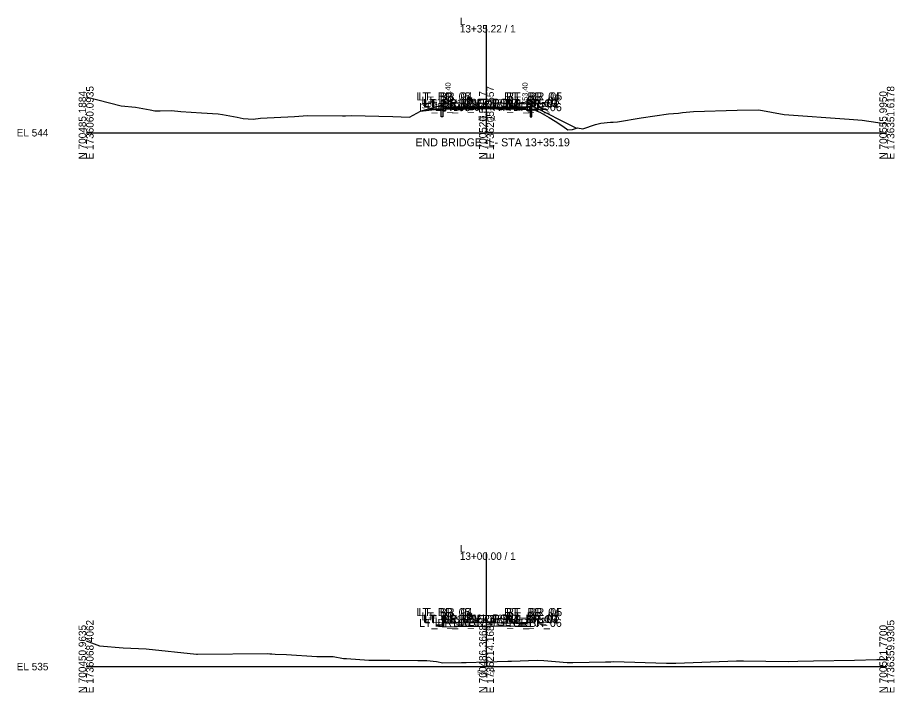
# Model space of a CAD drawing. Extents: x -26 to 697, y -10 to 2642.
# Drawn here: x -25.7 to 302.8, y 1390.3 to 1643.2 of the extents above; entities that cross this region are included whole.
import ezdxf

# ---------------------------------------------------------------- set-up
doc = ezdxf.new("R2010")
doc.units = 0
for name, color, linetype in [('Default', 7, 'Continuous'), ('Exist Cross Section Cell', 7, 'Continuous'), ('Exist XS Center Line Elevation Label', 7, 'Continuous'), ('Exist XS Ground Line', 7, 'Continuous'), ('Prop CMT Concrete Structures', 7, 'Continuous'), ('Prop CMT Guardrail SBG', 7, 'Continuous'), ('Prop CMT Pvmt Course 1', 7, 'Continuous'), ('Prop CMT Pvmt Course 2', 7, 'Continuous'), ('Prop CMT Pvmt Surface', 7, 'Continuous'), ('Prop CMT Pvmt Surface Shoulder', 7, 'Continuous'), ('Prop CMT Shld Paved Course 1', 7, 'Continuous'), ('Prop CMT Shld Paved Course 2', 7, 'Continuous'), ('Prop CMT Slope Grass', 7, 'Continuous'), ('Prop CMT Subgrade Earthwork', 7, 'Continuous'), ('Prop XS Hydro Elevations', 7, 'Continuous'), ('Prop XS SE Text', 7, 'Continuous'), ('Prop XS Side Slope Text', 7, 'Continuous')]:
    doc.layers.add(name, color=color, linetype=linetype)

msp = doc.modelspace()

# ---------------------------------------------------------------- linework, layer by layer
at = {"layer": 'Exist Cross Section Cell'}
for p, q in [((150, 1600), (150, 1640.35)), ((0, 1600), (150, 1600)), ((150, 1600), (300, 1600)), ((150, 1400), (150, 1442.78)), ((0, 1400), (150, 1400)), ((150, 1400), (300, 1400))]:
    msp.add_line(p, q, dxfattribs=at)
at = {"layer": 'Exist XS Center Line Elevation Label'}
for p, q in [((133.5, 1414.87), (133.5, 1416.22)), ((133.58, 1416.22), (133.58, 1418.91)), ((134.58, 1416.22), (134.58, 1418.91)), ((165.42, 1416.22), (165.42, 1418.91)), ((166.42, 1416.22), (166.42, 1418.91)), ((166.5, 1414.87), (166.5, 1416.22))]:
    msp.add_line(p, q, dxfattribs=at)
at = {"layer": 'Exist XS Ground Line'}
for points in [[(0, 1613.45), (13.1, 1610.13), (18.5, 1609.6), (23.97, 1608.58), (25.74, 1608.24), (27.68, 1608.25), (31.96, 1608.28), (35.46, 1607.94), (43.25, 1607.45), (49.53, 1607.02), (51.14, 1606.85), (56.59, 1605.78), (58.88, 1605.34), (62.57, 1605.06), (65.28, 1605.43), (78.08, 1606.05), (83, 1606.4), (96.09, 1606.37), (97.14, 1606.36), (99.25, 1606.45), (114.96, 1606.11), (121.2, 1605.8), (125.32, 1608.1), (133.81, 1609.09), (134.99, 1609.33), (138.11, 1609.4), (140.28, 1609.45), (143.28, 1609.41), (149.53, 1609.42), (150, 1609.41), (156.31, 1609.37), (159.15, 1609.48), (159.41, 1609.35), (160.65, 1609.15), (162.87, 1608.94), (165.72, 1608.86), (167.9, 1608.75), (169, 1608.07), (170, 1607.73), (173.49, 1605.72), (175.78, 1604.35), (178.62, 1602.48), (180.43, 1601.03), (182.17, 1601.27), (184.15, 1601.84), (186.07, 1601.52), (190.8, 1603.09), (192.86, 1603.63), (196.51, 1603.93), (197.51, 1604), (199.02, 1604.1), (207.98, 1605.6), (218.16, 1607.06), (221.92, 1607.36), (223.46, 1607.58), (227.61, 1607.92), (243.88, 1608.44), (252.01, 1608.52), (261.56, 1606.89), (285.88, 1605.07), (287.48, 1604.94), (290.69, 1604.67), (300, 1603.28)], [(0, 1409.61), (5.04, 1407.8), (13.87, 1407.06), (22.53, 1406.6), (41.36, 1404.69), (41.71, 1404.65), (68.09, 1404.85), (68.79, 1404.8), (69.54, 1404.83), (70.77, 1404.71), (75.02, 1404.55), (86.47, 1403.82), (92.61, 1403.8), (96.47, 1403.04), (97.58, 1402.99), (105.9, 1402.43), (113.82, 1402.43), (124.24, 1402.29), (127.66, 1402.24), (131.23, 1401.94), (133.68, 1401.41), (140.66, 1401.56), (142.41, 1401.57), (150, 1401.77), (157.96, 1401.97), (159.37, 1402), (168.95, 1402.44), (171.53, 1402.34), (180.24, 1401.48), (182.32, 1401.49), (194.54, 1401.81), (196.6, 1401.79), (197.52, 1401.85), (217.48, 1401.27), (218.69, 1401.26), (219.86, 1401.26), (220.97, 1401.24), (243.6, 1402.2), (244.94, 1402.19), (246.29, 1402.14), (263.04, 1401.95), (266.7, 1401.98), (272.51, 1402.19), (287.87, 1402.36), (296.21, 1402.61), (298.63, 1402.69), (300, 1402.69)]]:
    msp.add_lwpolyline(points, dxfattribs=at)
at = {"layer": 'Prop CMT Concrete Structures'}
for p, q in [((133.92, 1608.24), (134.58, 1608.24)), ((166.08, 1608.24), (165.42, 1608.24)), ((133.5, 1416.22), (133.58, 1416.22)), ((134.58, 1418.91), (133.58, 1418.91)), ((165.42, 1418.91), (166.42, 1418.91)), ((166.5, 1416.22), (166.42, 1416.22))]:
    msp.add_line(p, q, dxfattribs=at)
for points in [[(136.92, 1609.49), (134.58, 1609.4), (133.92, 1609.74)], [(133.92, 1609.74), (133.92, 1608.24)], [(134.58, 1609.4), (133.92, 1609.74)], [(134.58, 1608.24), (134.58, 1609.4)], [(165.42, 1609.4), (166.08, 1609.74)], [(165.42, 1608.24), (165.42, 1609.4)], [(166.08, 1609.74), (166.08, 1608.24)], [(150, 1416.53), (139, 1416.31), (134.58, 1416.22)], [(150, 1415.2), (150, 1416.53)], [(150, 1415.2), (150, 1416.53)], [(150, 1416.53), (161, 1416.31), (165.42, 1416.22)], [(133.5, 1414.87), (139, 1414.98), (150, 1415.2)], [(166.5, 1414.87), (161, 1414.98), (150, 1415.2)]]:
    msp.add_lwpolyline(points, dxfattribs=at)
at = {"layer": 'Prop CMT Guardrail SBG'}
for points in [[(132.98, 1605.9), (132.98, 1611.9)], [(132.98, 1611.9), (134.31, 1611.9), (134.58, 1611.61)], [(134.58, 1611.02), (134.31, 1610.73), (133.65, 1610.73)], [(133.65, 1610.73), (133.65, 1605.9)], [(134.58, 1611.61), (134.31, 1611.31)], [(134.31, 1611.31), (134.58, 1611.02)], [(167.02, 1611.9), (165.69, 1611.9), (165.42, 1611.61)], [(165.42, 1611.61), (165.69, 1611.31)], [(165.69, 1611.31), (165.42, 1611.02)], [(165.42, 1611.02), (165.69, 1610.73), (166.35, 1610.73)], [(166.35, 1610.73), (166.35, 1605.9)], [(167.02, 1605.9), (167.02, 1611.9)], [(133.65, 1605.9), (132.98, 1605.9)], [(166.35, 1605.9), (167.02, 1605.9)]]:
    msp.add_lwpolyline(points, dxfattribs=at)
at = {"layer": 'Prop CMT Pvmt Course 1'}
for points in [[(150, 1609.75), (139, 1609.53)], [(139, 1609.32), (150, 1609.54)], [(139, 1609.53), (139, 1609.32)], [(150, 1609.54), (150, 1609.75)], [(150, 1609.75), (161, 1609.53)], [(150, 1609.54), (150, 1609.75)], [(161, 1609.32), (150, 1609.54)], [(161, 1609.53), (161, 1609.32)]]:
    msp.add_lwpolyline(points, dxfattribs=at)
msp.add_lwpolyline([(150, 1609.54), (150, 1609.65), (150, 1609.65), (150, 1609.54)], close=True, dxfattribs=at)
msp.add_lwpolyline([(150, 1609.54), (150, 1609.65), (150, 1609.65), (150, 1609.54)], close=True, dxfattribs=at)
at = {"layer": 'Prop CMT Pvmt Course 2'}
for points in [[(150, 1609.54), (139, 1609.32)], [(139, 1609.32), (139, 1608.87)], [(139, 1608.87), (150, 1609.09)], [(150, 1609.09), (150, 1609.54)], [(150, 1609.09), (150, 1609.54)], [(150, 1609.54), (161, 1609.32)], [(161, 1608.87), (150, 1609.09)], [(161, 1609.32), (161, 1608.87)]]:
    msp.add_lwpolyline(points, dxfattribs=at)
at = {"layer": 'Prop CMT Pvmt Surface'}
for points in [[(150, 1609.75), (139, 1609.53)], [(150, 1609.75), (161, 1609.53)]]:
    msp.add_lwpolyline(points, dxfattribs=at)
at = {"layer": 'Prop CMT Pvmt Surface Shoulder'}
for points in [[(136.92, 1609.49), (134.58, 1609.4)], [(139, 1609.53), (136.92, 1609.49)], [(161, 1609.53), (163.08, 1609.49)], [(163.08, 1609.49), (165.42, 1609.4)]]:
    msp.add_lwpolyline(points, dxfattribs=at)
at = {"layer": 'Prop CMT Shld Paved Course 1'}
for points in [[(139, 1609.53), (136.92, 1609.49)], [(136.92, 1609.49), (136.92, 1609.28)], [(136.92, 1609.28), (139, 1609.32)], [(139, 1609.32), (139, 1609.53)], [(161, 1609.53), (163.08, 1609.49)], [(161, 1609.32), (161, 1609.53)], [(163.08, 1609.28), (161, 1609.32)], [(163.08, 1609.49), (163.08, 1609.28)]]:
    msp.add_lwpolyline(points, dxfattribs=at)
at = {"layer": 'Prop CMT Shld Paved Course 2'}
for points in [[(139, 1609.32), (136.92, 1609.28)], [(136.92, 1609.28), (136.92, 1609.07), (136.92, 1608.82)], [(136.92, 1608.82), (139, 1608.87)], [(139, 1608.87), (139, 1609.32)], [(161, 1609.32), (163.08, 1609.28)], [(161, 1608.87), (161, 1609.32)], [(163.08, 1608.82), (161, 1608.87)], [(163.08, 1609.28), (163.08, 1609.07), (163.08, 1608.82)]]:
    msp.add_lwpolyline(points, dxfattribs=at)
at = {"layer": 'Prop CMT Slope Grass'}
for points in [[(133.92, 1609.74), (133.15, 1610.14), (125.92, 1608.17)], [(166.08, 1609.74), (166.85, 1610.14), (183.71, 1601.71)]]:
    msp.add_lwpolyline(points, dxfattribs=at)
at = {"layer": 'Prop CMT Subgrade Earthwork'}
for p, q in [((133.92, 1608.24), (133.92, 1608.82)), ((134.58, 1608.24), (133.92, 1608.24)), ((165.42, 1608.24), (166.08, 1608.24)), ((166.08, 1608.24), (166.08, 1608.82))]:
    msp.add_line(p, q, dxfattribs=at)
for points in [[(133.92, 1608.82), (128.33, 1608.82)], [(134.58, 1608.24), (134.58, 1608.82)], [(136.92, 1608.82), (134.58, 1608.82)], [(139, 1608.87), (136.92, 1608.82)], [(136.92, 1608.82), (136.92, 1608.82)], [(150, 1609.09), (139, 1608.87)], [(150, 1609.09), (161, 1608.87)], [(161, 1608.87), (163.08, 1608.82)], [(163.08, 1608.82), (163.08, 1608.82)], [(163.08, 1608.82), (165.42, 1608.82)], [(165.42, 1608.24), (165.42, 1608.82)], [(166.08, 1608.82), (169.48, 1608.82)]]:
    msp.add_lwpolyline(points, dxfattribs=at)

# ---------------------------------------------------------------- texts
at = {"layer": 'Default'}
for s, height, p in [('LT_ BR_05', 3, (123.75, 1612.11)), ('LT_ BR_04', 3, (124.46, 1612.11)), ('LT_BR_03', 3, (125.65, 1610.53)), ('RT_ BR_04', 3, (156.64, 1612.11)), ('RT_ BR_05', 3, (157.4, 1612.11)), ('RT_BR_03', 3, (157.5, 1610.53)), ('LT_BR_06', 3, (124.71, 1608.08)), ('LT_BR_02', 3, (126.29, 1609.69)), ('LT_PV1_OEOT', 3, (126.6, 1609.53)), ('LT_BR_01', 3, (126.73, 1609.44)), ('LT_BR_07', 3, (130.58, 1608.2)), ('PV1_PGL', 3, (142.41, 1609.75)), ('BR_PGL', 3, (143.26, 1608.42)), ('RT_PV1_OEOT', 3, (148.42, 1609.53)), ('RT_BR_07', 3, (152.41, 1608.2)), ('RT_BR_02', 3, (156.96, 1609.69)), ('RT_BR_01', 3, (157.39, 1609.44)), ('RT_BR_06', 3, (158.37, 1608.08)), ('-', 0.0001, (0, 1600)), ('LT_ BR_05', 3, (123.75, 1418.89)), ('LT_ BR_04', 3, (124.46, 1418.89)), ('LT_BR_03', 3, (125.65, 1417.3)), ('LT_BR_02', 3, (126.29, 1416.47)), ('LT_PV1_OEOT', 3, (126.6, 1416.31)), ('LT_BR_01', 3, (126.73, 1416.22)), ('PV1_PGL', 3, (142.41, 1416.53)), ('RT_PV1_OEOT', 3, (148.42, 1416.31)), ('RT_ BR_04', 3, (156.64, 1418.89)), ('RT_BR_02', 3, (156.96, 1416.47)), ('RT_BR_01', 3, (157.39, 1416.22)), ('RT_ BR_05', 3, (157.4, 1418.89)), ('RT_BR_03', 3, (157.5, 1417.3)), ('LT_BR_06', 3, (124.71, 1414.86)), ('LT_BR_07', 3, (130.58, 1414.98)), ('BR_PGL', 3, (143.26, 1415.2)), ('RT_BR_07', 3, (152.41, 1414.98)), ('RT_BR_06', 3, (158.37, 1414.86)), ('-', 0.0001, (0, 1400))]:
    msp.add_text(s, height=height, dxfattribs=at).set_placement(p)
at = {"layer": 'Exist Cross Section Cell'}
for s, p in [('L', (140, 1640.35)), ('13+35.22 / 1', (140, 1637.55)), ('EL 544', (-26, 1598.6)), ('L', (140, 1442.78)), ('13+00.00 / 1', (140, 1439.98)), ('EL 535', (-26, 1398.6))]:
    msp.add_text(s, height=2.8, dxfattribs=at).set_placement(p)
for s, p in [('E 1736060.0935', (2.8, 1590)), ('E 1736205.8557', (152.8, 1590)), ('E 1736351.6178', (302.8, 1590)), ('N 700485.1884', (0, 1590)), ('N 700520.5917', (150, 1590)), ('N 700555.9950', (300, 1590)), ('E 1736068.4062', (2.8, 1390)), ('E 1736214.1684', (152.8, 1390)), ('E 1736359.9305', (302.8, 1390)), ('N 700450.9635', (0, 1390)), ('N 700486.3668', (150, 1390)), ('N 700521.7700', (300, 1390))]:
    msp.add_text(s, height=2.8, rotation=90, dxfattribs=at).set_placement(p)
at = {"layer": 'Exist XS Center Line Elevation Label'}
for s, p in [('553.41', (146.86, 1604.61)), ('536.77', (146.56, 1396.97))]:
    msp.add_text(s, height=1.6, dxfattribs=at).set_placement(p)
at = {"layer": 'Prop XS Hydro Elevations'}
for p in [(136.58, 1610.4), (165.42, 1610.4)]:
    msp.add_text('553.40', height=2, rotation=90, dxfattribs=at).set_placement(p)
at = {"layer": 'Prop XS SE Text'}
for rotation, p in [(1.1458, (140.98, 1610.57)), (358.8542, (152.02, 1610.71)), (1.1458, (140.98, 1417.35)), (358.8542, (152.02, 1417.49))]:
    msp.add_text('0.020', height=2, rotation=rotation, dxfattribs=at).set_placement(p)
at = {"layer": 'Prop XS Side Slope Text'}
for s, rotation, p in [('3.68:1', 15.147, (125.9, 1608.95)), ('2:1', 333.4349, (169.9, 1609.45))]:
    msp.add_text(s, height=2, rotation=rotation, dxfattribs=at).set_placement(p)
msp.add_text('END BRIDGE -L- STA 13+35.19', height=3, dxfattribs=at).set_placement((123.36, 1594.91))

doc.saveas('drawing.dxf')
